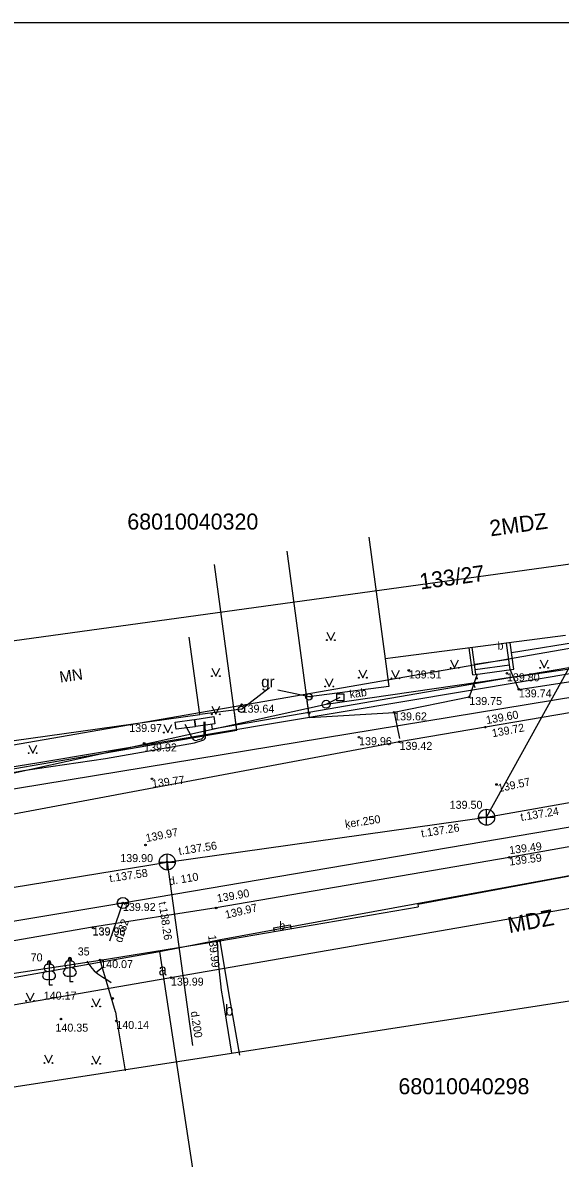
# Model space of a CAD drawing. Extents: x 728492 to 729038, y 272968 to 273171.
# Drawn here: x 728917.1 to 728950.7, y 273100 to 273170.9 of the extents above; entities that cross this region are included whole.
import ezdxf

# ---------------------------------------------------------------- set-up
doc = ezdxf.new("R2010")
doc.units = 0
for name, color, linetype in [('APGR_SARK_####_####_#', 7, 'Continuous'), ('BUVE_BDET_####_####_#', 7, 'Continuous'), ('BUVE_BDET_####_TKST_#', 7, 'Continuous'), ('BUVE_EKAS_####_####_#', 7, 'Continuous'), ('BUVE_EKAS_ADRS_TKST_#', 7, 'Continuous'), ('BUVE_EKAS_RAKS_TKST_#', 7, 'Continuous'), ('CELI_CAPM_####_####_#', 7, 'Continuous'), ('CELI_CMAL_####_####_#', 7, 'Continuous'), ('CELI_CSEG_####_TKST_#', 7, 'Continuous'), ('CELI_SEGL_####_####_#', 7, 'Continuous'), ('ELEK_ELEM_####_####_#', 7, 'Continuous'), ('ELEK_VADP_ZSPR_####_#', 7, 'Continuous'), ('ELEK_VADP_ZSPR_####_I', 7, 'Continuous'), ('ELEK_VADV_ZSPR_####_#', 7, 'Continuous'), ('ELEK_VADV_ZSPR_TKST_#', 7, 'Continuous'), ('Level 32', 7, 'Continuous'), ('NORB_ELEM_####_####_#', 7, 'Continuous'), ('NORB_ZOGS_BARJ_####_#', 7, 'Continuous'), ('NORB_ZOGS_KOKA_####_#', 7, 'Continuous'), ('RAMI_PLAN_####_TKST_#', 7, 'Continuous'), ('RAMI_UZMR_####_####_#', 7, 'Continuous'), ('RELJ_AATZ_####_TKST_#', 7, 'Continuous'), ('RELJ_ELEM_####_####_#', 7, 'Continuous'), ('RELJ_HORZ_KRIT_####_#', 7, 'Continuous'), ('ROBZ_KADS_####_TKST_#', 7, 'Continuous'), ('ROBZ_UZMR_####_####_#', 7, 'Continuous'), ('SAKK_KKAN_####_####_#', 7, 'Continuous'), ('SKAN_ELEM_####_####_#', 7, 'Continuous'), ('SKAN_VADP_PAST_####_#', 7, 'Continuous'), ('SKAN_VADP_PAST_TKST_#', 7, 'Continuous'), ('TERT_DIAM_####_TKST_#', 7, 'Continuous'), ('TERT_ELEM_####_####_#', 7, 'Continuous'), ('UDTK_ELEM_####_####_#', 7, 'Continuous'), ('UDTK_ELEM_####_TKST_#', 7, 'Continuous'), ('UDTK_VADP_UDEN_####_#', 7, 'Continuous'), ('UDTK_VADP_UDEN_TKST_#', 7, 'Continuous')]:
    doc.layers.add(name, color=color, linetype=linetype)

msp = doc.modelspace()

# ---------------------------------------------------------------- linework, layer by layer
at = {"layer": 'APGR_SARK_####_####_#'}
for points in [[(728962.51, 273133.798), (728824.842, 273109.886)], [(728964.826, 273117.961), (728827.017, 273094.024)]]:
    msp.add_lwpolyline(points, dxfattribs=at)
at = {"layer": 'BUVE_BDET_####_####_#'}
for p, q in [((728945.201, 273130.202), (728944.965, 273131.873)), ((728945.391, 273130.228), (728945.156, 273131.897)), ((728947.534, 273130.524), (728947.306, 273132.173)), ((728947.75, 273130.554), (728947.522, 273132.201)), ((728945.301, 273130.87), (728947.445, 273131.166)), ((728945.201, 273130.202), (728947.75, 273130.554)), ((728945.349, 273130.528), (728947.493, 273130.824)), ((728945.015, 273129.656), (728947.815, 273130.089)), ((728932.744, 273114.398), (728933.793, 273114.592)), ((728932.744, 273114.398), (728932.787, 273114.164)), ((728933.793, 273114.592), (728933.839, 273114.345))]:
    msp.add_line(p, q, dxfattribs=at)
at = {"layer": 'BUVE_EKAS_####_####_#'}
for p, q in [((728938.707, 273138.789), (728939.731, 273131.201)), ((728950.987, 273132.646), (728940.375, 273131.284)), ((728928.159, 273127.726), (728927.483, 273132.539)), ((728940.375, 273131.284), (728939.731, 273131.201)), ((728910.037, 273125.181), (728928.159, 273127.726)), ((728941.754, 273115.883), (728962.752, 273119.795)), ((728929.388, 273113.579), (728941.786, 273115.713)), ((728941.754, 273115.883), (728941.786, 273115.713)), ((728929.388, 273113.579), (728930.006, 273109.988)), ((728930.006, 273109.988), (728930.618, 273106.433))]:
    msp.add_line(p, q, dxfattribs=at)
at = {"layer": 'CELI_CAPM_####_####_#'}
msp.add_line((728963.075, 273121.548), (728947.473, 273118.795), dxfattribs=at)
for points in [[(728962.885, 273129.761), (728960.258, 273129.36), (728940.62, 273126.01)], [(728947.473, 273118.795), (728929.173, 273115.635), (728921.451, 273114.43)], [(728921.451, 273114.43), (728906.807, 273111.886), (728887.177, 273108.316), (728871.777, 273105.534), (728862.513, 273103.854), (728851.375, 273101.928), (728832.719, 273098.413), (728826.071, 273097.316), (728825.017, 273097.001), (728824.765, 273096.832), (728824.532, 273096.455), (728824.532, 273096.455), (728826.161, 273084.877), (728827.609, 273074.269)]]:
    msp.add_lwpolyline(points, dxfattribs=at)
at = {"layer": 'CELI_CMAL_####_####_#'}
for p, q in [((728934.999, 273127.535), (728933.598, 273137.914)), ((728930.461, 273126.743), (728929.065, 273137.091)), ((728957.034, 273133.096), (728947.609, 273131.578)), ((728948.069, 273129.288), (728962.958, 273131.569)), ((728934.964, 273127.794), (728934.862, 273128.552)), ((728930.444, 273126.872), (728930.308, 273127.882)), ((728905.649, 273122.465), (728927.067, 273126.15)), ((728922.881, 273109.141), (728921.935, 273112.38)), ((728929.49, 273110.51), (728929.589, 273109.91)), ((728929.589, 273109.91), (728930.137, 273106.573)), ((728922.881, 273109.141), (728922.951, 273108.713)), ((728922.951, 273108.713), (728923.482, 273105.453))]:
    msp.add_line(p, q, dxfattribs=at)
for points in [[(728948.069, 273129.288), (728947.534, 273130.524)], [(728945.475, 273130.229), (728944.976, 273128.81)], [(728945.222, 273129.688), (728945.313, 273129.411)], [(728944.976, 273128.81), (728940.282, 273127.851), (728940.62, 273126.21)], [(728934.999, 273127.535), (728940.282, 273127.851)], [(728927.067, 273126.15), (728930.461, 273126.743)], [(728940.62, 273126.01), (728905.191, 273119.377), (728848.564, 273109.818), (728825.164, 273106.226), (728823.68, 273107.224)], [(728915.742, 273111.435), (728921.935, 273112.38)]]:
    msp.add_lwpolyline(points, dxfattribs=at)
msp.add_arc((728965.191, 273115.146), 36.001, 182.53591, 187.39982, dxfattribs=at)
at = {"layer": 'CELI_SEGL_####_####_#'}
msp.add_lwpolyline([(728921.935, 273112.38), (728921.929, 273112.38), (728929.388, 273113.579)], dxfattribs=at)
at = {"layer": 'ELEK_ELEM_####_####_#'}
for points in [[(728937.145, 273128.578), (728936.699, 273128.578), (728936.699, 273129.018), (728937.145, 273129.018)], [(728926.603, 273127.239), (728927.793, 273127.398), (728927.853, 273126.952), (728926.663, 273126.793)], [(728927.838, 273127.406), (728929.025, 273127.586), (728929.092, 273127.141), (728927.906, 273126.961)]]:
    msp.add_lwpolyline(points, close=True, dxfattribs=at)
msp.add_circle((728936.036, 273128.36), 0.25, dxfattribs=at)
at = {"layer": 'ELEK_VADP_ZSPR_####_#'}
for points in [[(728951.576, 273130.701), (728946.768, 273129.874), (728931.098, 273127.179), (728928.944, 273126.808), (728928.895, 273127.096)], [(728936.036, 273128.36), (728936.922, 273128.797)]]:
    msp.add_lwpolyline(points, dxfattribs=at)
at = {"layer": 'ELEK_VADP_ZSPR_####_I'}
for p, q in [((728928.389, 273127.266), (728928.409, 273126.427)), ((728928.511, 273126.353), (728928.489, 273127.268)), ((728928.23, 273126.181), (728927.976, 273126.106)), ((728927.817, 273125.955), (728928.332, 273126.107))]:
    msp.add_line(p, q, dxfattribs=at)
for points in [[(728927.684, 273126.23), (728927.228, 273127.096)], [(728847.542, 273112.389), (728850.48, 273112.917), (728858.289, 273114.135), (728866.245, 273115.454), (728875.36, 273117.043), (728880.914, 273118.035), (728887.201, 273119.02), (728893.506, 273120.092), (728901.17, 273121.265), (728917.144, 273124.228), (728922.252, 273124.972), (728927.817, 273125.955)]]:
    msp.add_lwpolyline(points, dxfattribs=at)
for centre, start, end in [((728927.905, 273126.346), 207.75459, 286.45134), ((728928.159, 273126.421), 286.45134, 1.36735), ((728928.261, 273126.347), 286.45134, 1.36735)]:
    msp.add_arc(centre, 0.25, start, end, dxfattribs=at)
at = {"layer": 'ELEK_VADV_ZSPR_####_#'}
for p, q in [((728936.036, 273128.36), (728964.384, 273132.474)), ((728905.864, 273121.718), (728936.036, 273128.36))]:
    msp.add_line(p, q, dxfattribs=at)
at = {"layer": 'Level 32'}
msp.add_lwpolyline([(728921.088, 273112.311), (728921.164, 273112.204), (728921.271, 273112.051), (728921.404, 273111.877), (728921.557, 273111.703), (728921.789, 273111.516), (728922.101, 273111.308), (728922.405, 273111.12), (728922.615, 273110.988)], dxfattribs=at)
at = {"layer": 'NORB_ELEM_####_####_#'}
for centre in [(728934.964, 273128.82), (728930.745, 273128.042)]:
    msp.add_circle(centre, 0.202, dxfattribs=at)
at = {"layer": 'NORB_ZOGS_BARJ_####_#'}
for points in [[(728930.745, 273128.042), (728932.505, 273129.41)], [(728935.188, 273128.772), (728933.01, 273129.246)]]:
    msp.add_lwpolyline(points, dxfattribs=at)
at = {"layer": 'NORB_ZOGS_KOKA_####_#'}
msp.add_line((728930.745, 273128.042), (728928.159, 273127.726), dxfattribs=at)
msp.add_lwpolyline([(728939.731, 273131.201), (728939.949, 273129.466), (728934.964, 273128.82)], dxfattribs=at)
at = {"layer": 'RAMI_PLAN_####_TKST_#'}
msp.add_lwpolyline([(728765.305, 273170.927), (728765.305, 272986.902), (729038.383, 272986.902), (729038.383, 273170.927)], close=True, dxfattribs=at)
at = {"layer": 'RAMI_UZMR_####_####_#'}
msp.add_lwpolyline([(728688.721, 273058.407), (728702.149, 273066.922), (728733.452, 273072.937), (728813.127, 273088.247), (728815.181, 273072.879), (728831.342, 273076.994), (728831.817, 273091.35), (728930.137, 273106.573), (728962.389, 273111.567), (728966.363, 273103.835), (728988.796, 273109.153), (728985.811, 273141.417), (728955.146, 273144.603), (728957.616, 273137.975), (728904.333, 273130.641), (728847.677, 273120.095), (728823.483, 273119.793), (728790.036, 273112.558), (728726.814, 273102.175), (728686.914, 273096.216)], dxfattribs=at)
at = {"layer": 'RELJ_ELEM_####_####_#'}
for centre in [(728941.197, 273130.47), (728945.427, 273129.976), (728947.326, 273130.292), (728948.069, 273129.288), (728930.758, 273128.331), (728944.976, 273128.81), (728934.964, 273127.794), (728940.282, 273127.851), (728945.971, 273126.926), (728938.092, 273126.303), (728924.669, 273125.911), (728940.62, 273126.01), (728925.156, 273123.7), (728946.674, 273123.345), (728946.06, 273121.302), (728924.758, 273119.566), (728926.111, 273118.506), (728947.473, 273118.795), (728923.344, 273115.945), (728929.173, 273115.635), (728921.457, 273114.41), (728929.388, 273113.579), (728921.929, 273112.38), (728926.344, 273111.283), (728922.71, 273109.984), (728919.478, 273108.699), (728922.935, 273108.578)]:
    msp.add_circle(centre, 0.05, dxfattribs=at)
at = {"layer": 'RELJ_HORZ_KRIT_####_#'}
msp.add_line((728921.661, 273111.611), (728922.053, 273111.921), dxfattribs=at)
at = {"layer": 'ROBZ_UZMR_####_####_#'}
for p, q in [((728962.218, 273132.099), (728918.09, 273124.69)), ((728918.09, 273124.69), (728906.58, 273122.86)), ((728929.443, 273113.665), (728962.863, 273119.799)), ((728925.622, 273112.926), (728929.443, 273113.665)), ((728916.045, 273111.206), (728925.622, 273112.926)), ((728925.622, 273112.926), (728928.512, 273094.068))]:
    msp.add_line(p, q, dxfattribs=at)
at = {"layer": 'SAKK_KKAN_####_####_#'}
msp.add_lwpolyline([(728822.033, 273123.296), (728824.535, 273107.953), (728848.919, 273112.053), (728887.446, 273118.532), (728897.906, 273120.141), (728908.778, 273121.814), (728951.822, 273128.885)], dxfattribs=at)
at = {"layer": 'SKAN_ELEM_####_####_#'}
for p, q in [((728945.56, 273121.302), (728946.56, 273121.302)), ((728946.06, 273120.802), (728946.06, 273121.802)), ((728925.611, 273118.506), (728926.611, 273118.506)), ((728926.111, 273118.006), (728926.111, 273119.006))]:
    msp.add_line(p, q, dxfattribs=at)
for centre in [(728946.06, 273121.302), (728926.111, 273118.506)]:
    msp.add_circle(centre, 0.5, dxfattribs=at)
at = {"layer": 'SKAN_VADP_PAST_####_#'}
for points in [[(728946.06, 273121.302), (728952.446, 273132.863)], [(728926.111, 273118.506), (728946.06, 273121.302), (728961.809, 273124.096)], [(728886.872, 273111.928), (728911.07, 273116.044), (728926.111, 273118.506), (728927.684, 273107.043)]]:
    msp.add_lwpolyline(points, dxfattribs=at)
at = {"layer": 'TERT_ELEM_####_####_#'}
for p, q in [((728936.084, 273132.866), (728936.334, 273132.366)), ((728936.334, 273132.366), (728936.584, 273132.866)), ((728928.906, 273130.617), (728929.156, 273130.117)), ((728929.156, 273130.117), (728929.406, 273130.617)), ((728938.082, 273130.517), (728938.332, 273130.017)), ((728938.332, 273130.017), (728938.582, 273130.517)), ((728940.124, 273130.478), (728940.374, 273129.978)), ((728940.374, 273129.978), (728940.624, 273130.478)), ((728943.812, 273131.131), (728944.062, 273130.631)), ((728944.062, 273130.631), (728944.312, 273131.131)), ((728949.406, 273131.131), (728949.656, 273130.631)), ((728949.656, 273130.631), (728949.906, 273131.131)), ((728935.984, 273129.967), (728936.234, 273129.467)), ((728936.234, 273129.467), (728936.484, 273129.967)), ((728928.906, 273128.231), (728929.156, 273127.731)), ((728929.156, 273127.731), (728929.406, 273128.231)), ((728925.909, 273127.088), (728926.159, 273126.588)), ((728926.159, 273126.588), (728926.409, 273127.088)), ((728917.461, 273125.803), (728917.711, 273125.303)), ((728917.711, 273125.303), (728917.961, 273125.803)), ((728920.032, 273111.39), (728920.032, 273111.043)), ((728918.739, 273111.184), (728918.739, 273110.837)), ((728918.739, 273110.837), (728918.939, 273110.837)), ((728920.032, 273111.043), (728920.232, 273111.043)), ((728917.298, 273110.332), (728917.548, 273109.832)), ((728917.548, 273109.832), (728917.798, 273110.332)), ((728921.423, 273109.979), (728921.673, 273109.479)), ((728921.673, 273109.479), (728921.923, 273109.979)), ((728918.455, 273106.454), (728918.705, 273105.954)), ((728918.705, 273105.954), (728918.955, 273106.454)), ((728921.423, 273106.403), (728921.673, 273105.903)), ((728921.673, 273105.903), (728921.923, 273106.403))]:
    msp.add_line(p, q, dxfattribs=at)
for points in [[(728918.739, 273112.337), (728918.739, 273111.184)], [(728918.829, 273112.105), (728918.828, 273112.106)], [(728920.032, 273112.543), (728920.032, 273111.39)], [(728920.122, 273112.311), (728920.121, 273112.312)]]:
    msp.add_lwpolyline(points, dxfattribs=at)
for centre, radius in [((728936.084, 273132.366), 0.028), ((728936.584, 273132.366), 0.0263), ((728943.812, 273130.631), 0.028), ((728944.312, 273130.631), 0.0263), ((728949.405, 273130.631), 0.028), ((728949.905, 273130.631), 0.0263), ((728928.906, 273130.116), 0.028), ((728929.406, 273130.116), 0.0263), ((728938.081, 273130.016), 0.028), ((728938.581, 273130.016), 0.0263), ((728940.124, 273129.977), 0.028), ((728940.624, 273129.977), 0.0263), ((728935.984, 273129.466), 0.028), ((728936.484, 273129.466), 0.0263), ((728928.906, 273127.731), 0.028), ((728929.406, 273127.731), 0.0263), ((728925.909, 273126.588), 0.028), ((728926.409, 273126.588), 0.0263), ((728917.461, 273125.302), 0.028), ((728917.961, 273125.302), 0.0263), ((728917.297, 273109.831), 0.028), ((728917.797, 273109.831), 0.0263), ((728921.423, 273109.479), 0.028), ((728921.923, 273109.479), 0.0263), ((728918.455, 273105.953), 0.028), ((728918.955, 273105.953), 0.0263), ((728921.423, 273105.903), 0.028), ((728921.923, 273105.903), 0.0263)]:
    msp.add_circle(centre, radius, dxfattribs=at)
for centre, major_axis, ratio, start_param, end_param in [((728918.611, 273111.892), (-0.039, -0.212), 0.861323, 3.141593, 6.283185), ((728918.739, 273112.187), (0, -0.15), 0.707107, 3.14537, 5.287485), ((728918.739, 273112.187), (0, -0.15), 0.707107, 0.995701, 3.137816), ((728918.867, 273111.892), (0.039, -0.212), 0.861323, 0, 3.141593), ((728919.904, 273112.098), (-0.039, -0.212), 0.861323, 3.141593, 6.283185), ((728920.032, 273112.393), (0, -0.15), 0.707107, 3.14537, 5.287485), ((728920.032, 273112.393), (0, -0.15), 0.707107, 0.995701, 3.137816), ((728920.16, 273112.098), (0.039, -0.212), 0.861323, 0, 3.141593), ((728918.649, 273111.43), (0.307, 0.095), 0.814445, 1.570796, 4.752015), ((728918.829, 273111.43), (-0.307, 0.095), 0.814445, 1.531171, 4.712389), ((728919.942, 273111.636), (0.307, 0.095), 0.814445, 1.570796, 4.752015), ((728920.122, 273111.636), (-0.307, 0.095), 0.814445, 1.531171, 4.712389)]:
    msp.add_ellipse(centre, major_axis=major_axis, ratio=ratio, start_param=start_param, end_param=end_param, dxfattribs=at)
at = {"layer": 'UDTK_ELEM_####_####_#'}
for p, q in [((728922.994, 273115.944), (728923.696, 273115.944)), ((728923.344, 273115.944), (728923.344, 273115.945))]:
    msp.add_line(p, q, dxfattribs=at)
msp.add_circle((728923.345, 273115.944), 0.351, dxfattribs=at)
at = {"layer": 'UDTK_VADP_UDEN_####_#'}
for p in [(728955.625, 273121.419), (728922.523, 273113.582)]:
    msp.add_line(p, (728923.344, 273115.945), dxfattribs=at)
msp.add_lwpolyline([(728923.344, 273115.945), (728888.558, 273110.148), (728888.239, 273110.085)], dxfattribs=at)

# ---------------------------------------------------------------- texts
at = {"layer": 'BUVE_BDET_####_TKST_#'}
for p in [(728946.737, 273131.771), (728933.112, 273114.288)]:
    msp.add_text('b', height=0.5, dxfattribs=at).set_placement(p)
at = {"layer": 'BUVE_EKAS_ADRS_TKST_#'}
msp.add_text('133/27', height=1, rotation=7.762, dxfattribs=at).set_placement((728941.938, 273135.522))
at = {"layer": 'BUVE_EKAS_RAKS_TKST_#'}
for s, height, rotation, p in [('2MDZ', 1, 7.762, (728946.31, 273138.844)), ('MN', 0.7, 7.99417, (728919.435, 273129.707)), ('MDZ', 1, 10.44819, (728947.478, 273114.056))]:
    msp.add_text(s, height=height, rotation=rotation, dxfattribs=at).set_placement(p)
at = {"layer": 'CELI_CSEG_####_TKST_#'}
for s, p in [('gr', (728931.98, 273129.415)), ('a', (728925.567, 273111.435)), ('b', (728929.728, 273108.91))]:
    msp.add_text(s, height=0.7, dxfattribs=at).set_placement(p)
at = {"layer": 'ELEK_VADV_ZSPR_TKST_#'}
msp.add_text('kab', height=0.5, rotation=8.25832, dxfattribs=at).set_placement((728937.535, 273128.729))
at = {"layer": 'RELJ_AATZ_####_TKST_#'}
for s, p in [('139.51', (728941.197, 273129.97)), ('139.80', (728947.326, 273129.792)), ('139.74', (728948.069, 273128.788)), ('139.64', (728930.758, 273127.831)), ('139.75', (728944.976, 273128.31)), ('139.62', (728940.282, 273127.351)), (' 139.97', (728923.557, 273126.626)), ('139.96', (728938.092, 273125.803)), ('139.92', (728924.669, 273125.411)), ('139.42', (728940.62, 273125.51)), ('139.96', (728921.451, 273113.93)), ('139.93', (728921.457, 273113.91)), ('140.07', (728921.929, 273111.88)), ('139.99', (728926.344, 273110.783)), (' 140.17', (728918.216, 273109.911)), ('140.14', (728922.935, 273108.078)), (' 140.35', (728918.948, 273107.908))]:
    msp.add_text(s, height=0.5, dxfattribs=at).set_placement(p)
for s, rotation, p in [('139.60', 10.35721, (728946.068, 273127.117)), ('139.72', 10.76273, (728946.437, 273126.294)), ('139.77', 7.25042, (728925.191, 273123.146)), ('139.57', 12.23244, (728946.822, 273122.861)), ('139.97', 11.31902, (728924.818, 273119.746)), ('139.49', 7.58471, (728947.501, 273118.991)), ('139.59', 7.58471, (728947.501, 273118.278)), ('139.90', 9.76585, (728929.257, 273115.983)), ('139.97', 13.40314, (728929.79, 273114.962)), (' 139.99', 276.7684, (728928.642, 273114.099))]:
    msp.add_text(s, height=0.5, rotation=rotation, dxfattribs=at).set_placement(p)
at = {"layer": 'ROBZ_KADS_####_TKST_#'}
for s, p in [('68010040320', (728923.62, 273139.267)), ('68010040298', (728940.551, 273104))]:
    msp.add_text(s, height=1, dxfattribs=at).set_placement(p)
at = {"layer": 'SKAN_ELEM_####_####_#'}
for s, p in [('139.50', (728943.751, 273121.829)), ('139.90', (728923.182, 273118.501))]:
    msp.add_text(s, height=0.5, dxfattribs=at).set_placement(p)
at = {"layer": 'SKAN_VADP_PAST_TKST_#'}
for s, rotation, p in [('t.137.24', 9.174, (728948.211, 273121.068)), ('ķer.250', 8.499, (728937.253, 273120.624)), ('t.137.26', 9.174, (728942.007, 273120.04)), ('t.137.56', 8.499, (728926.856, 273118.943)), ('t.137.58', 8.499, (728922.534, 273117.239)), ('t.138.26', 278.559, (728925.57, 273115.985)), ('d.200', 278.559, (728927.576, 273109.15))]:
    msp.add_text(s, height=0.5, rotation=rotation, dxfattribs=at).set_placement(p)
at = {"layer": 'TERT_DIAM_####_TKST_#'}
for s, p in [('70', (728917.585, 273112.298)), ('35', (728920.524, 273112.669))]:
    msp.add_text(s, height=0.5, dxfattribs=at).set_placement(p)
at = {"layer": 'UDTK_ELEM_####_TKST_#'}
msp.add_text('139.92', height=0.5, dxfattribs=at).set_placement((728923.344, 273115.445))
at = {"layer": 'UDTK_VADP_UDEN_TKST_#'}
for s, rotation, p in [('d. 110', 9.45018, (728926.263, 273117.055)), ('d. 32', 71.668, (728923.269, 273113.432))]:
    msp.add_text(s, height=0.5, rotation=rotation, dxfattribs=at).set_placement(p)

doc.saveas('drawing.dxf')
